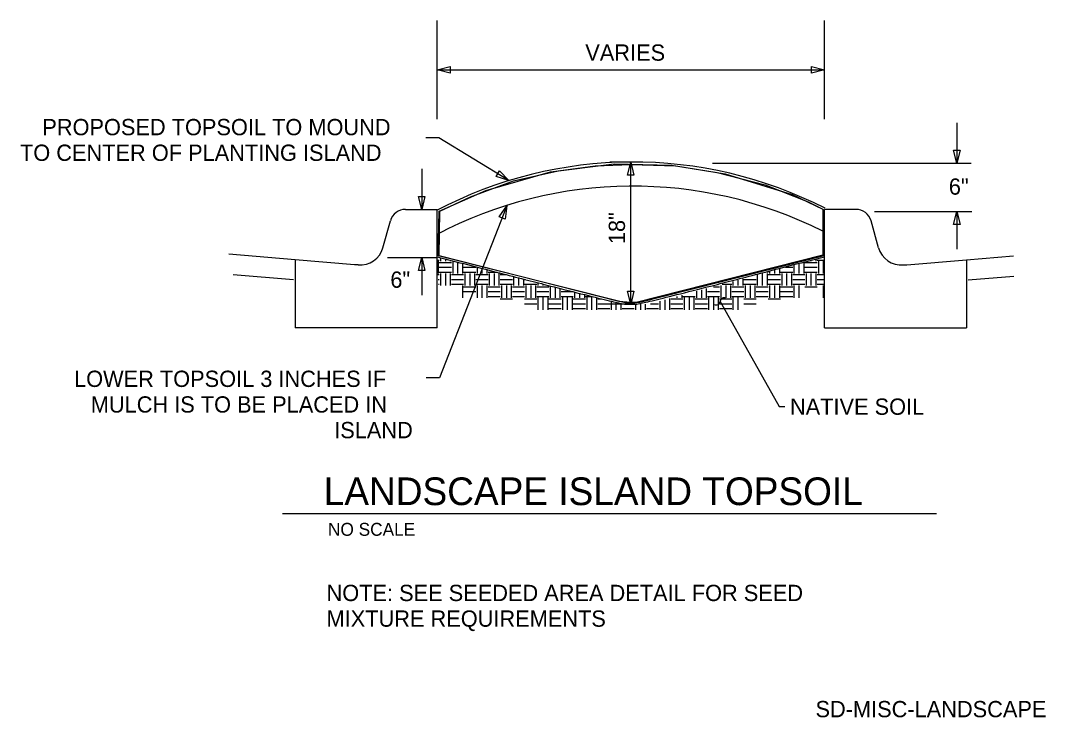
# Model space of a CAD drawing. Extents: x 9880.1 to 9945.9, y 10019.9 to 10064.6.
import ezdxf

# ---------------------------------------------------------------- set-up
doc = ezdxf.new("R2010")
doc.units = 0
for name, color, linetype in [('Default', 7, 'Continuous'), ('G-ANNO-TEXT', 7, 'Continuous'), ('G-ANNO-TTXT', 7, 'Continuous'), ('G-DETL-LINE', 7, 'Continuous'), ('G-DETL-OTLN', 7, 'Continuous'), ('G-DETL-PATT', 7, 'Continuous')]:
    doc.layers.add(name, color=color, linetype=linetype)

msp = doc.modelspace()

# ---------------------------------------------------------------- linework, layer by layer
at = {"layer": 'Default'}
for p, q in [((9910.978, 10048.408), (9910.978, 10048.396)), ((9912.458, 10048.011), (9912.526, 10048.011)), ((9913.943, 10047.648), (9913.943, 10047.62))]:
    msp.add_line(p, q, dxfattribs=at)
at = {"layer": 'G-ANNO-TEXT'}
for p, q in [((9906.845, 10058.283), (9906.845, 10064.606)), ((9931.689, 10058.283), (9931.689, 10064.606)), ((9906.845, 10061.445), (9931.689, 10061.445)), ((9919.379, 10055.534), (9917.919, 10055.534)), ((9919.267, 10046.429), (9919.267, 10055.534)), ((9906.845, 10052.504), (9906.845, 10052.504)), ((9940.192, 10052.372), (9940.192, 10049.955)), ((9905.862, 10049.419), (9905.862, 10047.002)), ((9919.267, 10046.429), (9917.293, 10046.429)), ((9896.922, 10033.016), (9938.892, 10033.016))]:
    msp.add_line(p, q, dxfattribs=at)
for points in [[(9907.678, 10061.236), (9906.845, 10061.445), (9907.678, 10061.653)], [(9930.856, 10061.653), (9931.689, 10061.445), (9930.856, 10061.236)], [(9919.059, 10054.7), (9919.267, 10055.534), (9919.475, 10054.7)], [(9939.983, 10051.539), (9940.192, 10052.372), (9940.4, 10051.539)], [(9905.653, 10048.586), (9905.862, 10049.419), (9906.07, 10048.586)], [(9919.475, 10047.262), (9919.267, 10046.429), (9919.059, 10047.262)]]:
    msp.add_lwpolyline(points, close=True, dxfattribs=at)
at = {"layer": 'G-ANNO-TTXT'}
for p, q in [((9940.192, 10058.057), (9940.192, 10055.457)), ((9905.862, 10055.105), (9905.862, 10052.504)), ((9924.515, 10055.457), (9941.109, 10055.457)), ((9934.916, 10052.372), (9941.147, 10052.372)), ((9903.666, 10049.419), (9906.817, 10049.419))]:
    msp.add_line(p, q, dxfattribs=at)
for points in [[(9940.4, 10056.29), (9940.192, 10055.457), (9939.983, 10056.29)], [(9906.07, 10053.337), (9905.862, 10052.504), (9905.653, 10053.337)], [(9910.83, 10052.034), (9911.329, 10052.733), (9911.218, 10051.881)], [(9910.83, 10052.034), (9911.329, 10052.733), (9911.218, 10051.881)]]:
    msp.add_lwpolyline(points, close=True, dxfattribs=at)
msp.add_lwpolyline([(9911.329, 10052.733), (9906.992, 10041.712), (9906.149, 10041.712)], dxfattribs=at)
at = {"layer": 'G-DETL-LINE'}
for p, q in [((9897.732, 10049.277), (9893.492, 10049.626)), ((9940.802, 10049.277), (9943.814, 10049.525)), ((9897.625, 10047.979), (9893.761, 10048.298)), ((9940.909, 10047.979), (9943.846, 10048.221))]:
    msp.add_line(p, q, dxfattribs=at)
at = {"layer": 'G-DETL-OTLN'}
for p, q in [((9904.825, 10052.504), (9906.845, 10052.504)), ((9906.845, 10044.91), (9906.845, 10052.504)), ((9933.709, 10052.504), (9931.689, 10052.504)), ((9931.689, 10044.91), (9931.689, 10052.504)), ((9903.371, 10050.045), (9903.85, 10051.763)), ((9935.163, 10050.045), (9934.684, 10051.763)), ((9901.551, 10048.958), (9897.732, 10049.277)), ((9897.732, 10049.277), (9897.732, 10044.91)), ((9936.983, 10048.958), (9940.802, 10049.277)), ((9940.802, 10049.277), (9940.802, 10044.91)), ((9901.782, 10048.939), (9901.551, 10048.958)), ((9936.752, 10048.939), (9936.983, 10048.958)), ((9906.845, 10044.91), (9897.732, 10044.91)), ((9931.689, 10044.91), (9940.802, 10044.91))]:
    msp.add_line(p, q, dxfattribs=at)
for points in [[(9911.452, 10054.355), (9906.958, 10057.086), (9906.116, 10057.086)], [(9924.999, 10046.608), (9928.785, 10039.874), (9929.15, 10039.874)]]:
    msp.add_lwpolyline(points, dxfattribs=at)
msp.add_lwpolyline([(9910.848, 10054.966), (9911.452, 10054.355), (9910.632, 10054.61)], close=True, dxfattribs=at)
msp.add_lwpolyline([(9910.848, 10054.966), (9911.452, 10054.355), (9910.632, 10054.61)], close=True, dxfattribs=at)
for centre, radius, start, end in [((9919.41, 10028.425), 27.111, 62.94442, 117.72036), ((9919.41, 10026.879), 27.111, 63.31232, 117.72036), ((9904.825, 10051.491), 1.013, 90, 164.42858), ((9933.709, 10051.491), 1.013, 15.57142, 90), ((9901.908, 10050.453), 1.519, 265.23634, 344.42863), ((9936.626, 10050.453), 1.519, 195.57137, 274.76366), ((9924.741, 10046.642), 0.26, 246.21107, 352.47128), ((9925.257, 10046.574), 0.26, 66.21107, 172.47128)]:
    msp.add_arc(centre, radius, start, end, dxfattribs=at)
msp.add_open_spline([(9906.845, 10049.467), (9918.545, 10046.429), (9919.267, 10046.429), (9919.989, 10046.429), (9931.689, 10049.467)], degree=2, dxfattribs=at)
at = {"layer": 'G-DETL-PATT'}
for p, q in [((9906.855, 10049.256), (9906.985, 10049.256)), ((9906.913, 10049.178), (9906.913, 10048.396)), ((9907.064, 10049.41), (9907.064, 10049.178)), ((9907.376, 10049.33), (9907.376, 10049.178)), ((9907.689, 10049.25), (9907.689, 10049.178)), ((9907.851, 10049.178), (9907.851, 10048.396)), ((9930.83, 10049.234), (9930.83, 10049.178)), ((9931.143, 10049.319), (9931.143, 10049.178)), ((9931.221, 10049.256), (9931.691, 10049.256)), ((9931.305, 10049.178), (9931.305, 10048.396)), ((9931.618, 10049.178), (9931.618, 10048.396)), ((9906.985, 10049.105), (9907.767, 10049.105)), ((9906.985, 10048.793), (9907.767, 10048.793)), ((9906.985, 10048.48), (9907.767, 10048.48)), ((9908.164, 10049.129), (9908.164, 10048.396)), ((9908.477, 10049.048), (9908.477, 10048.396)), ((9908.549, 10048.793), (9909.331, 10048.793)), ((9908.549, 10048.48), (9909.331, 10048.48)), ((9909.415, 10048.808), (9909.415, 10048.396)), ((9909.727, 10048.728), (9909.727, 10048.396)), ((9910.04, 10048.648), (9910.04, 10048.396)), ((9910.113, 10048.48), (9910.695, 10048.48)), ((9928.036, 10048.48), (9928.094, 10048.48)), ((9928.178, 10048.518), (9928.178, 10048.396)), ((9928.49, 10048.603), (9928.49, 10048.396)), ((9928.803, 10048.687), (9928.803, 10048.396)), ((9928.876, 10048.48), (9929.657, 10048.48)), ((9929.195, 10048.793), (9929.657, 10048.793)), ((9929.741, 10048.94), (9929.741, 10048.396)), ((9930.054, 10049.025), (9930.054, 10048.396)), ((9930.367, 10049.109), (9930.367, 10048.396)), ((9930.439, 10049.105), (9931.221, 10049.105)), ((9930.439, 10048.793), (9931.221, 10048.793)), ((9930.439, 10048.48), (9931.221, 10048.48)), ((9906.9, 10048.324), (9906.985, 10048.324)), ((9906.915, 10048.011), (9906.985, 10048.011)), ((9907.064, 10048.402), (9907.064, 10047.62)), ((9907.376, 10048.402), (9907.376, 10047.62)), ((9907.689, 10048.402), (9907.689, 10047.62)), ((9907.767, 10048.324), (9908.549, 10048.324)), ((9907.767, 10048.011), (9908.549, 10048.011)), ((9908.627, 10048.402), (9908.627, 10047.62)), ((9908.94, 10048.402), (9908.94, 10047.62)), ((9909.253, 10048.402), (9909.253, 10047.62)), ((9909.331, 10048.324), (9910.113, 10048.324)), ((9909.331, 10048.011), (9910.113, 10048.011)), ((9910.191, 10048.402), (9910.191, 10047.62)), ((9910.503, 10048.402), (9910.503, 10047.62)), ((9910.816, 10048.402), (9910.816, 10047.62)), ((9910.894, 10048.324), (9911.306, 10048.324)), ((9910.894, 10048.011), (9911.676, 10048.011)), ((9911.754, 10048.209), (9911.754, 10047.62)), ((9912.067, 10048.129), (9912.067, 10047.62)), ((9912.38, 10048.049), (9912.38, 10047.62)), ((9925.827, 10047.883), (9925.827, 10047.62)), ((9926.139, 10047.968), (9926.139, 10047.62)), ((9926.452, 10048.052), (9926.452, 10047.62)), ((9926.53, 10048.011), (9927.312, 10048.011)), ((9927.39, 10048.306), (9927.39, 10047.62)), ((9927.703, 10048.39), (9927.703, 10047.62)), ((9928.016, 10048.402), (9928.016, 10047.62)), ((9928.094, 10048.324), (9928.876, 10048.324)), ((9928.094, 10048.011), (9928.876, 10048.011)), ((9928.954, 10048.402), (9928.954, 10047.62)), ((9929.266, 10048.402), (9929.266, 10047.62)), ((9929.579, 10048.402), (9929.579, 10047.62)), ((9929.657, 10048.324), (9930.439, 10048.324)), ((9929.657, 10048.011), (9930.439, 10048.011)), ((9930.517, 10048.402), (9930.517, 10047.62)), ((9930.83, 10048.402), (9930.83, 10047.62)), ((9931.143, 10048.402), (9931.143, 10047.62)), ((9931.221, 10048.324), (9931.699, 10048.324)), ((9931.221, 10048.011), (9931.702, 10048.011)), ((9906.93, 10047.698), (9906.985, 10047.698)), ((9907.767, 10047.698), (9908.549, 10047.698)), ((9908.477, 10047.62), (9908.477, 10046.838)), ((9908.549, 10047.547), (9909.331, 10047.547)), ((9908.549, 10047.235), (9909.331, 10047.235)), ((9909.331, 10047.698), (9910.113, 10047.698)), ((9909.415, 10047.62), (9909.415, 10046.838)), ((9909.727, 10047.62), (9909.727, 10046.838)), ((9910.04, 10047.62), (9910.04, 10046.838)), ((9910.113, 10047.547), (9910.894, 10047.547)), ((9910.113, 10047.235), (9910.894, 10047.235)), ((9910.894, 10047.698), (9911.676, 10047.698)), ((9910.978, 10047.62), (9910.978, 10046.838)), ((9911.291, 10047.62), (9911.291, 10046.838)), ((9911.604, 10047.62), (9911.604, 10046.838)), ((9911.676, 10047.547), (9912.458, 10047.547)), ((9911.676, 10047.235), (9912.458, 10047.235)), ((9912.458, 10047.698), (9913.24, 10047.698)), ((9912.542, 10047.62), (9912.542, 10046.838)), ((9912.855, 10047.62), (9912.855, 10046.838)), ((9913.167, 10047.62), (9913.167, 10046.838)), ((9913.24, 10047.547), (9914.022, 10047.547)), ((9913.24, 10047.235), (9914.022, 10047.235)), ((9913.318, 10047.808), (9913.318, 10047.62)), ((9913.631, 10047.728), (9913.631, 10047.62)), ((9914.105, 10047.606), (9914.105, 10046.838)), ((9914.418, 10047.526), (9914.418, 10046.838)), ((9914.731, 10047.446), (9914.731, 10046.838)), ((9914.803, 10047.235), (9915.556, 10047.235)), ((9915.669, 10047.206), (9915.669, 10046.838)), ((9923.487, 10047.252), (9923.487, 10046.838)), ((9923.8, 10047.336), (9923.8, 10046.838)), ((9924.112, 10047.421), (9924.112, 10046.838)), ((9924.185, 10047.235), (9924.967, 10047.235)), ((9924.582, 10047.547), (9924.967, 10047.547)), ((9924.888, 10047.63), (9924.888, 10047.62)), ((9925.051, 10047.62), (9925.051, 10046.838)), ((9925.141, 10047.698), (9925.748, 10047.698)), ((9925.363, 10047.62), (9925.363, 10046.838)), ((9925.676, 10047.62), (9925.676, 10046.838)), ((9925.748, 10047.547), (9926.53, 10047.547)), ((9925.748, 10047.235), (9926.53, 10047.235)), ((9926.53, 10047.698), (9927.312, 10047.698)), ((9926.614, 10047.62), (9926.614, 10046.838)), ((9926.927, 10047.62), (9926.927, 10046.838)), ((9927.24, 10047.62), (9927.24, 10046.838)), ((9927.312, 10047.547), (9928.094, 10047.547)), ((9927.312, 10047.235), (9928.094, 10047.235)), ((9928.094, 10047.698), (9928.876, 10047.698)), ((9928.178, 10047.62), (9928.178, 10046.838)), ((9928.49, 10047.62), (9928.49, 10046.838)), ((9928.803, 10047.62), (9928.803, 10046.838)), ((9928.876, 10047.547), (9929.657, 10047.547)), ((9928.876, 10047.235), (9929.657, 10047.235)), ((9929.657, 10047.698), (9930.439, 10047.698)), ((9929.741, 10047.62), (9929.741, 10046.838)), ((9930.054, 10047.62), (9930.054, 10046.838)), ((9930.439, 10047.547), (9931.221, 10047.547)), ((9931.221, 10047.698), (9931.704, 10047.698)), ((9931.618, 10047.62), (9931.618, 10046.838)), ((9910.113, 10046.922), (9910.894, 10046.922)), ((9910.894, 10046.766), (9911.676, 10046.766)), ((9911.676, 10046.922), (9912.458, 10046.922)), ((9912.458, 10046.766), (9913.24, 10046.766)), ((9913.24, 10046.922), (9914.022, 10046.922)), ((9913.318, 10046.844), (9913.318, 10046.062)), ((9913.631, 10046.844), (9913.631, 10046.062)), ((9913.943, 10046.844), (9913.943, 10046.062)), ((9914.022, 10046.766), (9914.803, 10046.766)), ((9914.803, 10046.922), (9915.585, 10046.922)), ((9914.881, 10046.844), (9914.881, 10046.062)), ((9915.194, 10046.844), (9915.194, 10046.062)), ((9915.507, 10046.844), (9915.507, 10046.062)), ((9915.585, 10046.766), (9916.367, 10046.766)), ((9915.982, 10047.126), (9915.982, 10046.838)), ((9916.294, 10047.046), (9916.294, 10046.838)), ((9916.367, 10046.922), (9916.777, 10046.922)), ((9916.445, 10046.844), (9916.445, 10046.062)), ((9916.758, 10046.844), (9916.758, 10046.062)), ((9917.07, 10046.844), (9917.07, 10046.062)), ((9917.149, 10046.766), (9917.388, 10046.766)), ((9918.009, 10046.606), (9918.009, 10046.062)), ((9918.321, 10046.526), (9918.321, 10046.062)), ((9921.136, 10046.617), (9921.136, 10046.062)), ((9921.449, 10046.701), (9921.449, 10046.062)), ((9921.761, 10046.786), (9921.761, 10046.062)), ((9921.839, 10046.766), (9922.621, 10046.766)), ((9922.236, 10046.914), (9922.236, 10046.838)), ((9922.549, 10046.998), (9922.549, 10046.838)), ((9922.621, 10046.922), (9923.403, 10046.922)), ((9922.699, 10046.844), (9922.699, 10046.062)), ((9923.012, 10046.844), (9923.012, 10046.062)), ((9923.325, 10046.844), (9923.325, 10046.062)), ((9923.403, 10046.766), (9924.185, 10046.766)), ((9924.185, 10046.922), (9924.967, 10046.922)), ((9924.263, 10046.844), (9924.263, 10046.062)), ((9924.576, 10046.844), (9924.576, 10046.062)), ((9924.888, 10046.844), (9924.888, 10046.062)), ((9924.967, 10046.766), (9925.748, 10046.766)), ((9925.748, 10046.922), (9926.53, 10046.922)), ((9925.827, 10046.844), (9925.827, 10046.062)), ((9926.139, 10046.844), (9926.139, 10046.062)), ((9926.53, 10046.766), (9927.312, 10046.766)), ((9927.312, 10046.922), (9928.094, 10046.922)), ((9928.094, 10046.766), (9928.876, 10046.766)), ((9928.876, 10046.922), (9929.657, 10046.922)), ((9912.458, 10046.453), (9913.24, 10046.453)), ((9914.022, 10046.453), (9914.803, 10046.453)), ((9914.022, 10046.14), (9914.803, 10046.14)), ((9915.585, 10046.453), (9916.367, 10046.453)), ((9915.585, 10046.14), (9916.367, 10046.14)), ((9917.149, 10046.453), (9917.93, 10046.453)), ((9917.149, 10046.14), (9917.93, 10046.14)), ((9918.634, 10046.446), (9918.634, 10046.062)), ((9918.712, 10046.14), (9919.494, 10046.14)), ((9919.572, 10046.42), (9919.572, 10046.062)), ((9919.885, 10046.42), (9919.885, 10046.062)), ((9920.198, 10046.42), (9920.198, 10046.062)), ((9920.276, 10046.14), (9921.058, 10046.14)), ((9920.529, 10046.453), (9921.058, 10046.453)), ((9921.839, 10046.453), (9922.621, 10046.453)), ((9921.839, 10046.14), (9922.621, 10046.14)), ((9923.403, 10046.453), (9924.185, 10046.453)), ((9923.403, 10046.14), (9924.185, 10046.14)), ((9924.967, 10046.453), (9925.748, 10046.453)), ((9924.967, 10046.14), (9925.748, 10046.14)), ((9926.53, 10046.453), (9927.312, 10046.453))]:
    msp.add_line(p, q, dxfattribs=at)
for points in [[(9906.989, 10052.396), (9909.98, 10053.715), (9914.128, 10054.906), (9918.213, 10055.421), (9921.879, 10055.325), (9925.32, 10054.777), (9929.63, 10053.458), (9931.591, 10052.525), (9931.591, 10049.499), (9919.853, 10046.539), (9919.37, 10046.474), (9918.92, 10046.506), (9906.925, 10049.532)], [(9907.021, 10052.396), (9908.983, 10053.297), (9911.749, 10054.327), (9914.611, 10054.971), (9916.991, 10055.292), (9919.274, 10055.389), (9922.168, 10055.292), (9924.806, 10054.874), (9927.893, 10054.069), (9930.659, 10052.975), (9931.591, 10052.525), (9931.591, 10049.564), (9919.628, 10046.539), (9919.274, 10046.539), (9918.502, 10046.603), (9906.989, 10049.532)]]:
    msp.add_lwpolyline(points, close=True, dxfattribs=at)

# ---------------------------------------------------------------- texts
at = {"layer": 'G-ANNO-TEXT'}
for s, height, p in [('VARIES', 1.044, (9916.354, 10062.03)), ('PROPOSED TOPSOIL TO MOUND', 1.044, (9881.521, 10057.254)), ('TO CENTER OF PLANTING ISLAND', 1.044, (9880.091, 10055.61)), ('LOWER TOPSOIL 3 INCHES IF', 1.044, (9883.558, 10041.121)), (' MULCH IS TO BE PLACED IN', 1.044, (9884.242, 10039.477)), ('NATIVE SOIL', 1.044, (9929.483, 10039.336)), (' ISLAND', 1.044, (9899.858, 10037.833)), ('NO SCALE', 0.828, (9899.846, 10031.581)), ('NOTE: SEE SEEDED AREA DETAIL FOR SEED ', 1.044, (9899.756, 10027.397)), ('MIXTURE REQUIREMENTS', 1.044, (9899.756, 10025.753)), ('SD-MISC-LANDSCAPE', 1.044, (9931.12, 10019.951))]:
    msp.add_text(s, height=height, dxfattribs=at).set_placement(p)
for s, rotation, p in [('6"', 360, (9939.674, 10053.444)), ('18"', 90, (9918.9, 10050.273)), ('6"', 360, (9903.848, 10047.478))]:
    msp.add_text(s, height=1.044, rotation=rotation, dxfattribs=at).set_placement(p)
at = {"layer": 'G-ANNO-TTXT'}
msp.add_text('LANDSCAPE ISLAND TOPSOIL', height=1.776, dxfattribs=at).set_placement((9899.576, 10033.547))

doc.saveas('drawing.dxf')
